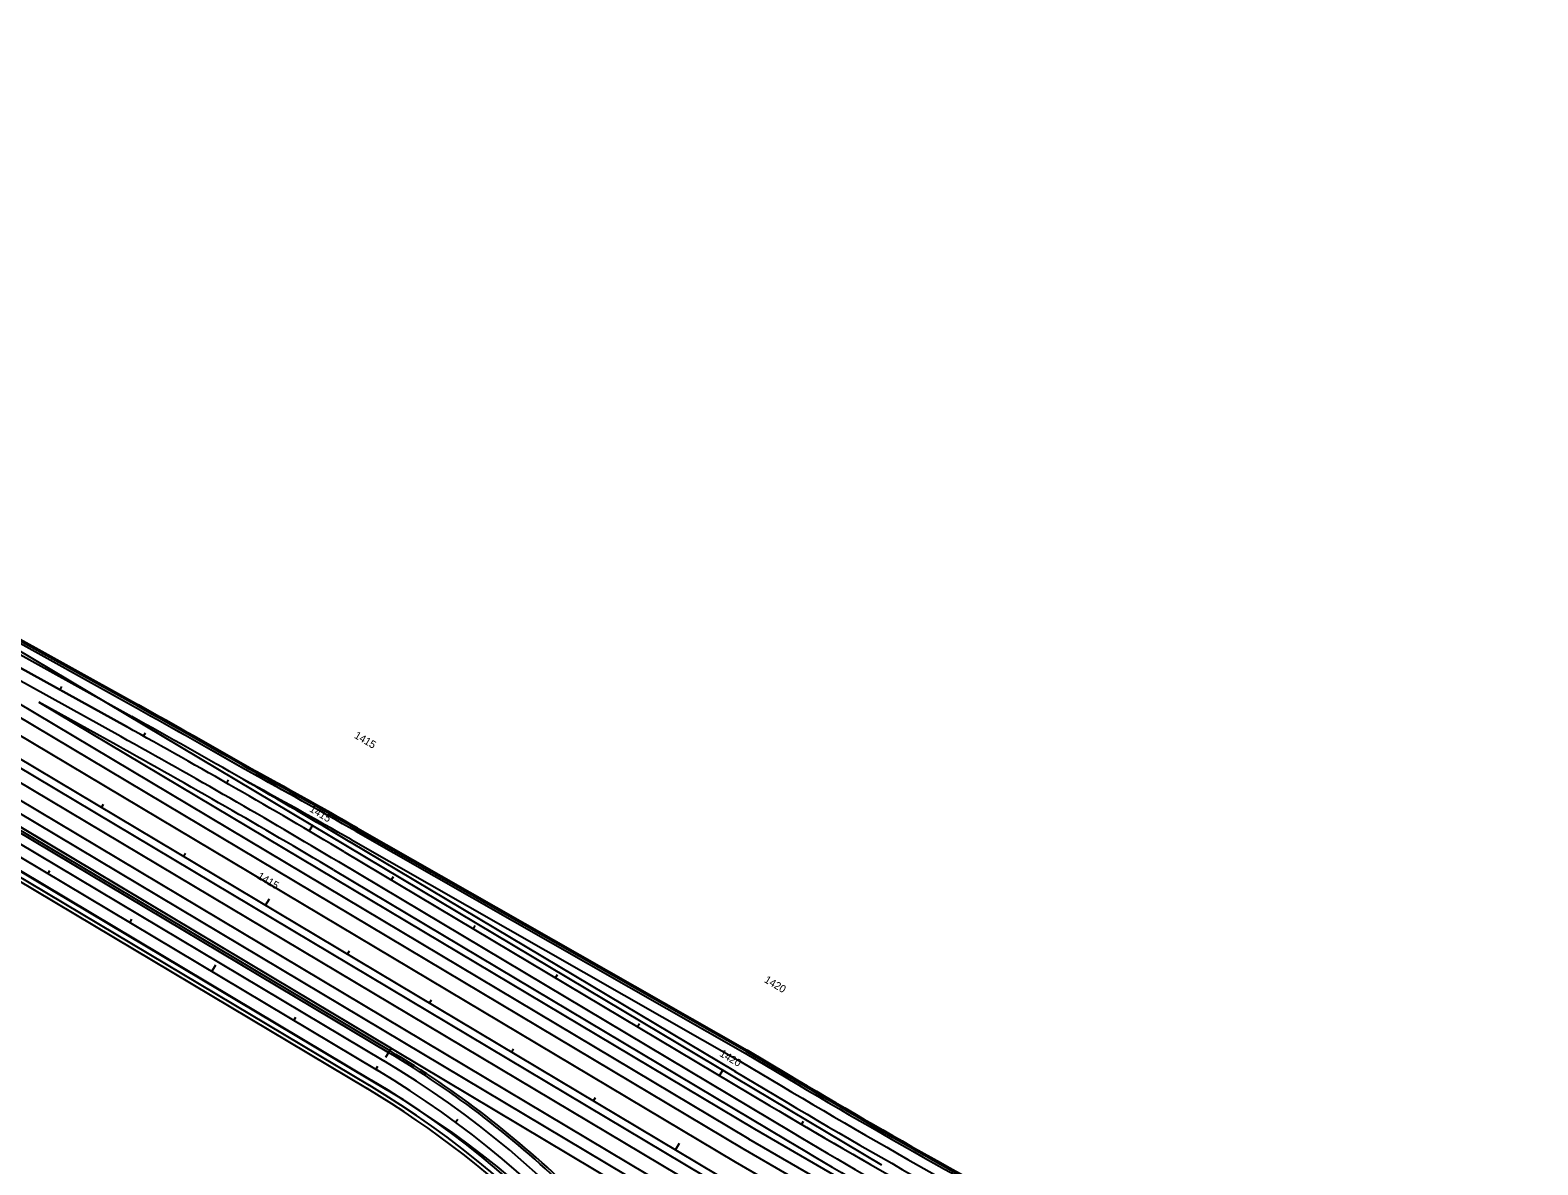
# Model space of a CAD drawing. Extents: x 2339272 to 2351734, y 366540 to 375057.
# Drawn here: x 2347572 to 2349150, y 368697 to 369885 of the extents above; entities that cross this region are included whole.
import ezdxf

# ---------------------------------------------------------------- set-up
doc = ezdxf.new("R2010")
doc.units = 0
for name, color, linetype in [('RD_HC_Cl', 7, 'Continuous'), ('RD_HC_CL_Rel', 7, 'Continuous'), ('RD_HC_Data_Tic', 7, 'Continuous'), ('RD_HC_Data_Tic_Rel', 7, 'Continuous'), ('RD_HC_TX_Rel_Sta50', 7, 'Continuous'), ('RD_HC_TX_Sta50', 7, 'Continuous'), ('RD_PD_Final_LnLine', 7, 'Continuous'), ('RD_PD_Final_TrvlWay', 7, 'Continuous'), ('RD_PD_GR', 7, 'Continuous'), ('RD_PD_MedBWall', 7, 'Continuous'), ('RD_PD_MedGR', 7, 'Continuous'), ('RD_PD_NOISE-WALL-GM', 7, 'Continuous'), ('RD_PD_PaveShd', 7, 'Continuous')]:
    doc.layers.add(name, color=color, linetype=linetype)

msp = doc.modelspace()

# ---------------------------------------------------------------- linework, layer by layer
at = {"layer": 'RD_HC_Cl'}
for p, q in [((2346281.6, 369885.4), (2351112.4, 367003.2)), ((2346606.5, 369804.5), (2348463.1, 368696.8)), ((2346606.5, 369804.5), (2348463.1, 368696.8)), ((2346606.5, 369804.5), (2348463.1, 368696.8)), ((2346606.5, 369804.5), (2348463.1, 368696.8))]:
    msp.add_line(p, q, dxfattribs=at)
at = {"layer": 'RD_HC_CL_Rel'}
for p, q in [((2346236.3, 369809.5), (2347935.6, 368795.6)), ((2346990.8, 369533.5), (2347672.4, 369155.9)), ((2347900.5, 369024.7), (2348345.9, 368759))]:
    msp.add_line(p, q, dxfattribs=at)
for centre, radius, start, end in [((2343690.2, 361967.9), 8217.3, 59.17851, 61.01367), ((2347423.3, 367936.8), 1000, 22.7108, 59.1785), ((2351938.6, 374780.7), 7012, 239.17851, 240.64281)]:
    msp.add_arc(centre, radius, start, end, dxfattribs=at)
at = {"layer": 'RD_HC_Data_Tic'}
for p, q in [((2347646.2, 369071.2), (2347648.3, 369074.7)), ((2347732.1, 369020), (2347734.1, 369023.4)), ((2347818, 368968.8), (2347822.1, 368975.6)), ((2347903.9, 368917.5), (2347905.9, 368921)), ((2347989.7, 368866.3), (2347991.8, 368869.7)), ((2348075.6, 368815.1), (2348077.7, 368818.5)), ((2348161.5, 368763.8), (2348163.5, 368767.3)), ((2348247.4, 368712.6), (2348251.5, 368719.5))]:
    msp.add_line(p, q, dxfattribs=at)
at = {"layer": 'RD_HC_Data_Tic_Rel'}
for p, q in [((2347602.9, 369194.4), (2347604.9, 369197.9)), ((2347690.4, 369145.9), (2347692.3, 369149.4)), ((2347777.4, 369096.7), (2347779.4, 369100.2)), ((2347863.9, 369046.4), (2347867.9, 369053.3)), ((2347590.1, 369001.8), (2347592.1, 369005.2)), ((2347949.8, 368995.3), (2347951.9, 368998.7)), ((2347676, 368950.5), (2347678, 368954)), ((2348035.7, 368944.1), (2348037.7, 368947.5)), ((2347761.8, 368899.3), (2347765.9, 368906.2)), ((2348121.6, 368892.8), (2348123.6, 368896.3)), ((2347847.7, 368848.1), (2347849.8, 368851.5)), ((2348207.4, 368841.6), (2348209.5, 368845)), ((2347933.6, 368796.8), (2347935.6, 368800.3)), ((2348293.3, 368790.4), (2348297.4, 368797.2)), ((2348016.9, 368741.6), (2348019.3, 368744.8)), ((2348379.3, 368739.2), (2348381.3, 368742.7))]:
    msp.add_line(p, q, dxfattribs=at)
at = {"layer": 'RD_PD_Final_LnLine'}
for p, q in [((2346262.5, 369853.5), (2348279.8, 368650)), ((2346236.3, 369809.5), (2347935.6, 368795.6)), ((2346236.7, 369794.6), (2347945.2, 368775.3)), ((2346236.7, 369794.6), (2347945.2, 368775.3)), ((2346236.7, 369794.6), (2347945.2, 368775.3)), ((2346236.7, 369794.6), (2347945.2, 368775.3)), ((2347672.4, 369155.9), (2346990.8, 369533.5)), ((2346978.7, 369512.8), (2348317.9, 368713.8)), ((2347900.5, 369024.7), (2348345.9, 368759)), ((2348310.4, 368794.1), (2347906.4, 369035.2)), ((2348309.1, 368794.9), (2348352, 368769.3)), ((2348317.8, 368713.8), (2348620.8, 368538.7))]:
    msp.add_line(p, q, dxfattribs=at)
for centre, radius, start, end in [((2343690.2, 361967.9), 8217.3, 59.17851, 61.01367), ((2343690.2, 361967.9), 8229.3, 59.17851, 60.07911), ((2347423.3, 367936.8), 1000, 22.7108, 59.1785), ((2347432.8, 367916.5), 1000, 22.4559, 59.1785), ((2347432.8, 367916.5), 1000, 22.4559, 59.1785), ((2347432.8, 367916.5), 1000, 22.4559, 59.1785), ((2347432.8, 367916.5), 1000, 22.4559, 59.1785), ((2351938.6, 374780.7), 7000, 239.17851, 245.88247), ((2351938.6, 374780.7), 7012, 239.17851, 242.08949)]:
    msp.add_arc(centre, radius, start, end, dxfattribs=at)
at = {"layer": 'RD_PD_Final_TrvlWay'}
for p, q in [((2346256.4, 369843.2), (2348273.5, 368639.7)), ((2346242.4, 369819.8), (2347941.8, 368805.9)), ((2346217.6, 369806.6), (2347929.5, 368785.3)), ((2346996.8, 369543.9), (2347678.2, 369166.4)), ((2346984.8, 369523.1), (2348324.1, 368724.1)), ((2347666.5, 369145.4), (2347390, 369298.6)), ((2347907.7, 369037.5), (2348315.2, 368805.2)), ((2347894.4, 369014.4), (2348368.9, 368731.3)), ((2348315.2, 368805.2), (2348358.2, 368779.6)), ((2348323.8, 368724.2), (2348626.9, 368549))]:
    msp.add_line(p, q, dxfattribs=at)
for centre, radius, start, end in [((2343690.2, 361967.9), 8229.3, 60.07911, 61.01367), ((2343690.2, 361967.9), 8205.3, 59.17851, 61.01367), ((2343906.6, 362012.6), 8084.4, 60.3362, 61.25122), ((2347423.3, 367936.8), 1012, 22.7108, 59.1785), ((2347423.3, 367936.8), 988, 22.7108, 59.1785), ((2351938.6, 374780.7), 6988, 239.17851, 245.88247), ((2352567.6, 375768.6), 8194.7, 239.17851, 240.4151)]:
    msp.add_arc(centre, radius, start, end, dxfattribs=at)
at = {"layer": 'RD_PD_GR'}
msp.add_line((2347001.1, 369327.6), (2347924.4, 368776.7), dxfattribs=at)
msp.add_arc((2347423.3, 367936.8), 978, 30.6678, 59.1785, dxfattribs=at)
at = {"layer": 'RD_PD_MedBWall'}
for p, q in [((2347683, 369175.2), (2347001.8, 369552.6)), ((2347684.2, 369177.2), (2347002.9, 369554.6)), ((2346753.4, 369526.6), (2347946.9, 368814.5)), ((2346754.6, 369528.6), (2347948.1, 368816.5)), ((2347912.6, 369046.2), (2348320.4, 368813.8)), ((2347913.8, 369048.2), (2348321.5, 368815.8)), ((2347946.9, 368814.5), (2347948.1, 368816.5)), ((2348321.4, 368815.9), (2348364.5, 368790.2)), ((2348320.2, 368813.9), (2348363.3, 368788.2))]:
    msp.add_line(p, q, dxfattribs=at)
for centre, radius, start, end in [((2343690.2, 361967.9), 8239.3, 60.08103, 61.01367), ((2343690.2, 361967.9), 8241.7, 60.08036, 61.01367), ((2343906.6, 362012.6), 8094.4, 60.3362, 61.24927), ((2343906.6, 362012.6), 8096.7, 60.3362, 61.24994), ((2347423.3, 367936.8), 1024.3, 45.5561, 59.1785), ((2347423.3, 367936.8), 1022, 45.5561, 59.1785), ((2351938.6, 374780.7), 6978, 239.17851, 245.88247), ((2351938.6, 374780.7), 6975.7, 239.17851, 245.88247)]:
    msp.add_arc(centre, radius, start, end, dxfattribs=at)
at = {"layer": 'RD_PD_MedGR'}
msp.add_line((2347144.9, 369361), (2349123.2, 368180.7), dxfattribs=at)
at = {"layer": 'RD_PD_NOISE-WALL-GM'}
for p, q in [((2347684.2, 369177.2), (2347002.9, 369554.6)), ((2347684.9, 369178.5), (2347003.7, 369555.9)), ((2347913.8, 369048.2), (2348321.5, 368815.8)), ((2347914.5, 369049.5), (2348322.3, 368817.1)), ((2348322.1, 368817.2), (2348365.3, 368791.5))]:
    msp.add_line(p, q, dxfattribs=at)
for centre, radius, start, end in [((2343690.2, 361967.9), 8243.2, 60.08036, 61.01367), ((2343690.2, 361967.9), 8241.7, 60.08036, 61.01367), ((2343906.6, 362012.6), 8096.7, 60.3362, 61.24994), ((2343906.6, 362012.6), 8098.2, 60.3362, 61.24994), ((2351938.6, 374780.7), 6974.2, 239.17851, 242.2042)]:
    msp.add_arc(centre, radius, start, end, dxfattribs=at)
at = {"layer": 'RD_PD_PaveShd'}
for p, q in [((2346247.5, 369828.4), (2347946.9, 368814.5)), ((2346250.2, 369832.9), (2347949.6, 368819)), ((2346250.2, 369832.9), (2348267.5, 368629.3)), ((2347683, 369175.2), (2347001.8, 369552.6)), ((2347129.1, 369404.4), (2348309.7, 368700)), ((2347107.4, 369368.1), (2348288, 368663.7)), ((2347117.1, 369263), (2347926.4, 368780.2)), ((2347580.8, 369181.5), (2348330, 368734.5)), ((2347661.7, 369136.7), (2347580.8, 369181.5)), ((2347912.6, 369046.2), (2348320.2, 368813.9)), ((2347889.2, 369005.8), (2348363.8, 368722.7)), ((2347949.6, 368819), (2347943.8, 368809.4)), ((2348320.4, 368813.8), (2348363.3, 368788.2)), ((2348330, 368734.5), (2348633, 368559.4)), ((2348309.8, 368700), (2348612.7, 368524.9))]:
    msp.add_line(p, q, dxfattribs=at)
for centre, radius, start, end in [((2343690.2, 361967.9), 8239.3, 60.07911, 61.01367), ((2343690.2, 361967.9), 8195.3, 59.17851, 61.01367), ((2343906.6, 362012.6), 8094.4, 60.3362, 61.25122), ((2351938.6, 374780.7), 6978, 239.17851, 245.88247), ((2347423.3, 367936.8), 982, 22.7108, 59.1785), ((2352567.6, 375768.6), 8204.7, 239.17851, 240.4151)]:
    msp.add_arc(centre, radius, start, end, dxfattribs=at)

# ---------------------------------------------------------------- texts
at = {"layer": 'RD_HC_TX_Rel_Sta50'}
for s, rotation, p in [('1415', 329.4754, (2347910.2, 369144.5)), ('1415', 329.1785, (2347808.6, 368997.2)), ('1420', 329.1785, (2348339.5, 368888.6))]:
    msp.add_text(s, height=8, rotation=rotation, dxfattribs=at).set_placement(p)
at = {"layer": 'RD_HC_TX_Sta50'}
for s, p in [('1415', (2347863.3, 369067.5)), ('1420', (2348292.7, 368811.3))]:
    msp.add_text(s, height=8, rotation=329.1785, dxfattribs=at).set_placement(p)

doc.saveas('drawing.dxf')
